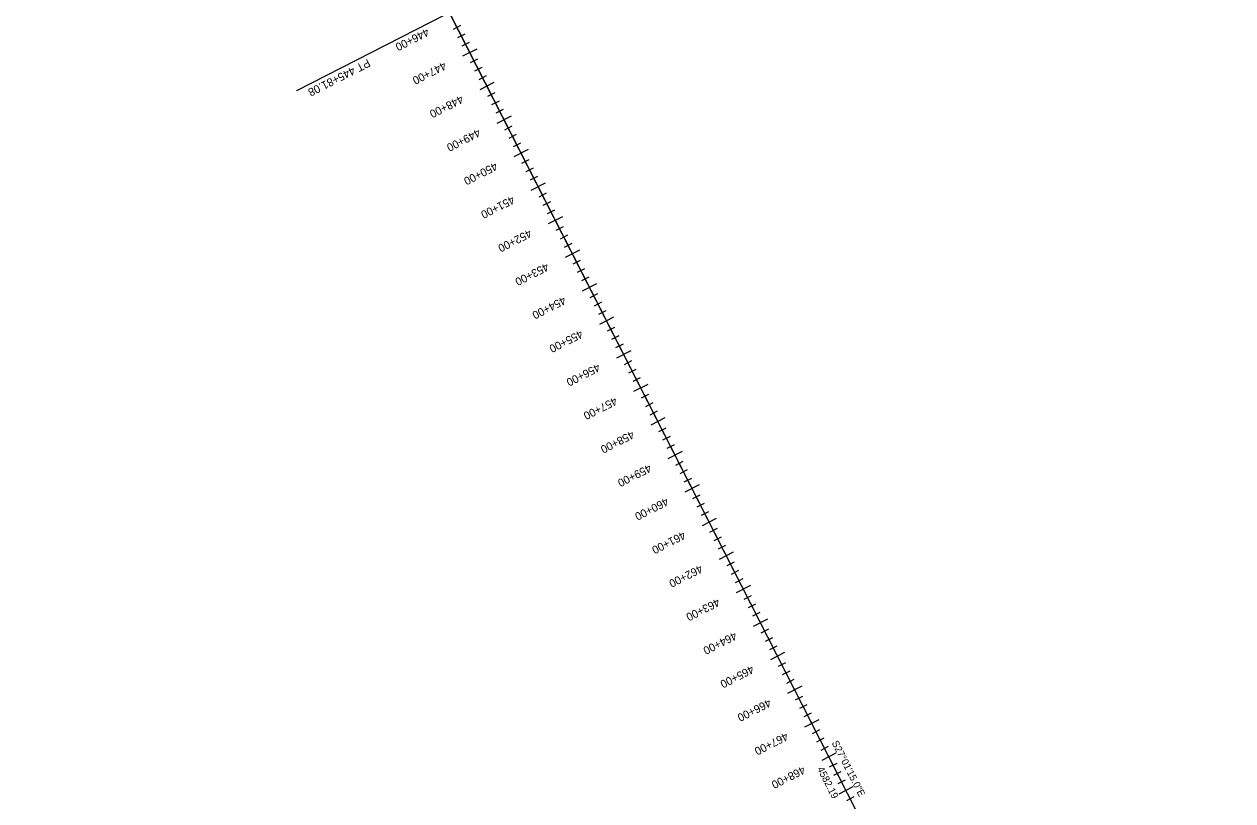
# Model space of a CAD drawing. Extents: x 2823077 to 2858057, y 1248786 to 1289821.
# Drawn here: x 2853238 to 2856449, y 1258236 to 1260299 of the extents above; entities that cross this region are included whole.
import ezdxf

# ---------------------------------------------------------------- set-up
doc = ezdxf.new("R2010")
doc.units = 0
for name, color, linetype in [('_CIVIL_CONSTRUCTION', 7, 'Continuous'), ('Default', 7, 'Continuous'), ('TL_Earth Shoulder Sub', 7, 'Continuous'), ('TL_End Condition Hinge', 7, 'Continuous'), ('TL_Pavement Centerline Sub', 7, 'Continuous'), ('TL_Pavement Edge', 7, 'Continuous'), ('TL_Pavement Edge Sub', 7, 'Continuous'), ('TL_Shoulder Edge', 7, 'Continuous')]:
    doc.layers.add(name, color=color, linetype=linetype)

msp = doc.modelspace()

# ---------------------------------------------------------------- linework, layer by layer
at = {"layer": '_CIVIL_CONSTRUCTION'}
msp.add_line((2854367.5, 1260328.9), (2856449.3, 1256246.9), dxfattribs=at)
at = {"layer": 'Default'}
msp.add_line((2853237.7, 1262544.3), (2855418.4, 1258268.3), dxfattribs=at)
at = {"layer": 'TL_Earth Shoulder Sub'}
msp.add_line((2853961.3, 1260121.8), (2853961.3, 1260121.8), dxfattribs=at)
at = {"layer": 'TL_Pavement Centerline Sub'}
for p, q in [((2854440.6, 1260232.7), (2854402.7, 1260213.4)), ((2854486, 1260143.6), (2854448.1, 1260124.3)), ((2854531.4, 1260054.5), (2854493.6, 1260035.2)), ((2854576.8, 1259965.4), (2854539, 1259946.1)), ((2854622.3, 1259876.4), (2854584.4, 1259857.1)), ((2854667.7, 1259787.3), (2854629.9, 1259768)), ((2854713.1, 1259698.2), (2854675.3, 1259678.9)), ((2854758.6, 1259609.1), (2854720.7, 1259589.8)), ((2854804, 1259520), (2854766.2, 1259500.7)), ((2854849.4, 1259430.9), (2854811.6, 1259411.6)), ((2854894.9, 1259341.9), (2854857, 1259322.6)), ((2854940.3, 1259252.8), (2854902.5, 1259233.5)), ((2854985.7, 1259163.7), (2854947.9, 1259144.4)), ((2855031.2, 1259074.6), (2854993.3, 1259055.3)), ((2855076.6, 1258985.5), (2855038.8, 1258966.2)), ((2855122, 1258896.4), (2855084.2, 1258877.1)), ((2855167.5, 1258807.3), (2855129.6, 1258788)), ((2855212.9, 1258718.3), (2855175, 1258699)), ((2855258.3, 1258629.2), (2855220.5, 1258609.9)), ((2855303.8, 1258540.1), (2855265.9, 1258520.8)), ((2855349.2, 1258451), (2855311.3, 1258431.7)), ((2855394.6, 1258361.9), (2855356.8, 1258342.6)), ((2855440, 1258272.8), (2855402.2, 1258253.5))]:
    msp.add_line(p, q, dxfattribs=at)
at = {"layer": 'TL_Pavement Edge Sub'}
for p, q in [((2854397.3, 1260294.8), (2854377.6, 1260284.8)), ((2854408.6, 1260272.5), (2854389, 1260262.5)), ((2854420, 1260250.3), (2854400.3, 1260240.2)), ((2854442.7, 1260205.7), (2854423, 1260195.7)), ((2854454.1, 1260183.5), (2854434.4, 1260173.4)), ((2854465.4, 1260161.2), (2854445.8, 1260151.2)), ((2854488.1, 1260116.7), (2854468.5, 1260106.6)), ((2854499.5, 1260094.4), (2854479.8, 1260084.3)), ((2854510.9, 1260072.1), (2854491.2, 1260062.1)), ((2854533.6, 1260027.6), (2854513.9, 1260017.5)), ((2854544.9, 1260005.3), (2854525.3, 1259995.3)), ((2854556.3, 1259983), (2854536.6, 1259973)), ((2854579, 1259938.5), (2854559.3, 1259928.5)), ((2854590.4, 1259916.2), (2854570.7, 1259906.2)), ((2854601.7, 1259893.9), (2854582.1, 1259883.9)), ((2854624.4, 1259849.4), (2854604.8, 1259839.4)), ((2854635.8, 1259827.1), (2854616.1, 1259817.1)), ((2854647.2, 1259804.9), (2854627.5, 1259794.8)), ((2854669.9, 1259760.3), (2854650.2, 1259750.3)), ((2854681.2, 1259738), (2854661.6, 1259728)), ((2854692.6, 1259715.8), (2854672.9, 1259705.7)), ((2854715.3, 1259671.2), (2854695.6, 1259661.2)), ((2854726.7, 1259649), (2854707, 1259638.9)), ((2854738, 1259626.7), (2854718.4, 1259616.7)), ((2854760.7, 1259582.1), (2854741.1, 1259572.1)), ((2854772.1, 1259559.9), (2854752.4, 1259549.8)), ((2854783.5, 1259537.6), (2854763.8, 1259527.6)), ((2854806.2, 1259493.1), (2854786.5, 1259483)), ((2854817.5, 1259470.8), (2854797.9, 1259460.8)), ((2854828.9, 1259448.5), (2854809.2, 1259438.5)), ((2854851.6, 1259404), (2854831.9, 1259393.9)), ((2854863, 1259381.7), (2854843.3, 1259371.7)), ((2854874.3, 1259359.4), (2854854.6, 1259349.4)), ((2854897, 1259314.9), (2854877.4, 1259304.9)), ((2854908.4, 1259292.6), (2854888.7, 1259282.6)), ((2854919.7, 1259270.4), (2854900.1, 1259260.3)), ((2854942.5, 1259225.8), (2854922.8, 1259215.8)), ((2854953.8, 1259203.5), (2854934.2, 1259193.5)), ((2854965.2, 1259181.3), (2854945.5, 1259171.2)), ((2854987.9, 1259136.7), (2854968.2, 1259126.7)), ((2854999.3, 1259114.5), (2854979.6, 1259104.4)), ((2855010.6, 1259092.2), (2854990.9, 1259082.2)), ((2855033.3, 1259047.6), (2855013.7, 1259037.6)), ((2855044.7, 1259025.4), (2855025, 1259015.3)), ((2855056, 1259003.1), (2855036.4, 1258993.1)), ((2855078.8, 1258958.6), (2855059.1, 1258948.5)), ((2855090.1, 1258936.3), (2855070.4, 1258926.3)), ((2855101.5, 1258914), (2855081.8, 1258904)), ((2855124.2, 1258869.5), (2855104.5, 1258859.4)), ((2855135.5, 1258847.2), (2855115.9, 1258837.2)), ((2855146.9, 1258824.9), (2855127.2, 1258814.9)), ((2855169.6, 1258780.4), (2855150, 1258770.4)), ((2855181, 1258758.1), (2855161.3, 1258748.1)), ((2855192.3, 1258735.8), (2855172.7, 1258725.8)), ((2855215.1, 1258691.3), (2855195.4, 1258681.3)), ((2855226.4, 1258669), (2855206.7, 1258659)), ((2855237.8, 1258646.8), (2855218.1, 1258636.7)), ((2855260.5, 1258602.2), (2855240.8, 1258592.2)), ((2855271.8, 1258579.9), (2855252.2, 1258569.9)), ((2855283.2, 1258557.7), (2855263.5, 1258547.6)), ((2855305.9, 1258513.1), (2855286.2, 1258503.1)), ((2855317.3, 1258490.9), (2855297.6, 1258480.8)), ((2855328.6, 1258468.6), (2855309, 1258458.6)), ((2855351.3, 1258424.1), (2855331.7, 1258414)), ((2855362.7, 1258401.8), (2855343, 1258391.8)), ((2855374.1, 1258379.5), (2855354.4, 1258369.5)), ((2855396.8, 1258335), (2855377.1, 1258324.9)), ((2855408.1, 1258312.7), (2855388.5, 1258302.7)), ((2855419.5, 1258290.4), (2855399.8, 1258280.4)), ((2855442.2, 1258245.9), (2855422.5, 1258235.9))]:
    msp.add_line(p, q, dxfattribs=at)
at = {"layer": 'TL_Shoulder Edge'}
msp.add_line((2854358, 1260324.1), (2853961.3, 1260121.8), dxfattribs=at)

# ---------------------------------------------------------------- texts
at = {"layer": 'TL_Earth Shoulder Sub'}
for s, p in [('PT', (2854150.5, 1260207)), ('445+81.08', (2854110.5, 1260186.6))]:
    msp.add_text(s, height=21.36, rotation=207.0208, dxfattribs=at).set_placement(p)
at = {"layer": 'TL_End Condition Hinge'}
for s, p in [('446+00', (2854307.1, 1260288.8)), ('447+00', (2854352.6, 1260199.7)), ('448+00', (2854398, 1260110.7)), ('449+00', (2854443.4, 1260021.6)), ('450+00', (2854488.8, 1259932.5)), ('451+00', (2854534.3, 1259843.4)), ('452+00', (2854579.7, 1259754.3)), ('453+00', (2854625.1, 1259665.2)), ('454+00', (2854670.6, 1259576.2)), ('455+00', (2854716, 1259487.1)), ('456+00', (2854761.4, 1259398)), ('457+00', (2854806.9, 1259308.9)), ('458+00', (2854852.3, 1259219.8)), ('459+00', (2854897.7, 1259130.7)), ('460+00', (2854943.2, 1259041.7)), ('461+00', (2854988.6, 1258952.6)), ('462+00', (2855034, 1258863.5)), ('463+00', (2855079.5, 1258774.4)), ('464+00', (2855124.9, 1258685.3)), ('465+00', (2855170.3, 1258596.2)), ('466+00', (2855215.8, 1258507.2)), ('467+00', (2855261.2, 1258418.1)), ('468+00', (2855306.6, 1258329))]:
    msp.add_text(s, height=21.26, rotation=207.0208, dxfattribs=at).set_placement(p)
at = {"layer": 'TL_Pavement Edge'}
for s, height, p in [('S27°01\'15.0"E', 18.898, (2855382.7, 1258389.9)), ('4582.19', 18.9, (2855344.1, 1258320.5))]:
    msp.add_text(s, height=height, rotation=297.0208, dxfattribs=at).set_placement(p)

doc.saveas('drawing.dxf')
